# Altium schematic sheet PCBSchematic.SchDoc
size Letter; SheetNumber: 1; SheetTotal: 1
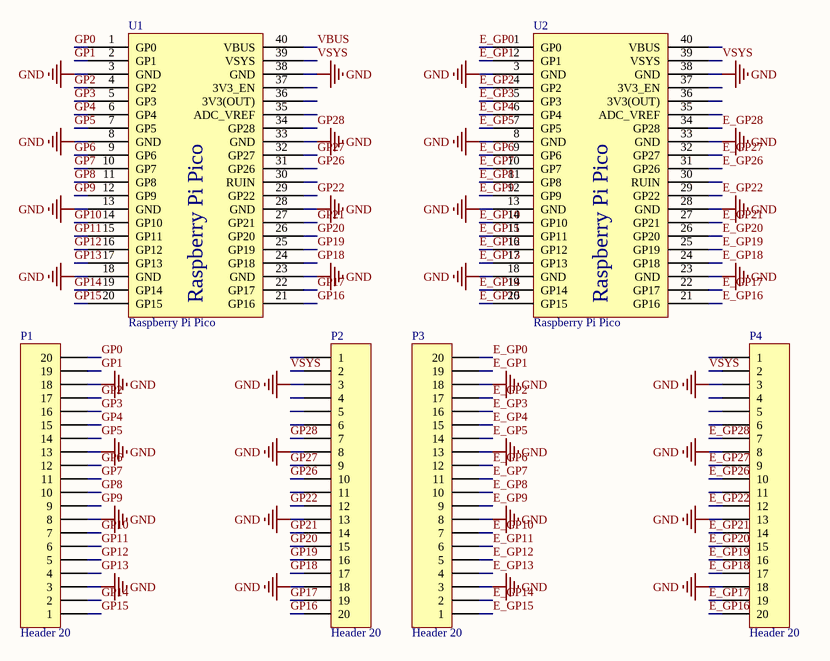
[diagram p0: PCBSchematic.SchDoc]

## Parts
P1  Header 20  [HDR1X20]
P2  Header 20  [HDR1X20]
P3  Header 20  [HDR1X20]
P4  Header 20  [HDR1X20]
U1  Raspberry Pi Pico  [Raspberry Pi Pico]
U2  Raspberry Pi Pico  [Raspberry Pi Pico]

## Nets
GND: P1.3 P1.8 P1.13 P1.18 P2.3 P2.8 P2.13 P2.18 P3.3 P3.8 P3.13 P3.18 P4.3 P4.8 P4.13 P4.18 U1.3(GND) U1.8(GND) U1.13(GND) U1.18(GND) U1.23(GND) U1.28(GND) U1.33(GND) U1.38(GND) U2.3(GND) U2.8(GND) U2.13(GND) U2.18(GND) U2.23(GND) U2.28(GND) U2.33(GND) U2.38(GND)
E_GP0: P3.20 U2.1(GP0)
E_GP1: P3.19 U2.2(GP1)
E_GP2: P3.17 U2.4(GP2)
E_GP3: P3.16 U2.5(GP3)
E_GP4: P3.15 U2.6(GP4)
E_GP5: P3.14 U2.7(GP5)
E_GP6: P3.12 U2.9(GP6)
E_GP7: P3.11 U2.10(GP7)
E_GP8: P3.10 U2.11(GP8)
E_GP9: P3.9 U2.12(GP9)
E_GP10: P3.7 U2.14(GP10)
E_GP11: P3.6 U2.15(GP11)
E_GP12: P3.5 U2.16(GP12)
E_GP13: P3.4 U2.17(GP13)
E_GP14: P3.2 U2.19(GP14)
E_GP15: P3.1 U2.20(GP15)
E_GP16: P4.20 U2.21(GP16)
E_GP17: P4.19 U2.22(GP17)
E_GP18: P4.17 U2.24(GP18)
E_GP19: P4.16 U2.25(GP19)
E_GP20: P4.15 U2.26(GP20)
E_GP21: P4.14 U2.27(GP21)
E_GP22: P4.12 U2.29(GP22)
E_GP26: P4.10 U2.31(GP26)
E_GP27: P4.9 U2.32(GP27)
E_GP28: P4.7 U2.34(GP28)
GP0: P1.20 U1.1(GP0)
GP1: P1.19 U1.2(GP1)
GP2: P1.17 U1.4(GP2)
GP3: P1.16 U1.5(GP3)
GP4: P1.15 U1.6(GP4)
GP5: P1.14 U1.7(GP5)
GP6: P1.12 U1.9(GP6)
GP7: P1.11 U1.10(GP7)
GP8: P1.10 U1.11(GP8)
GP9: P1.9 U1.12(GP9)
GP10: P1.7 U1.14(GP10)
GP11: P1.6 U1.15(GP11)
GP12: P1.5 U1.16(GP12)
GP13: P1.4 U1.17(GP13)
GP14: P1.2 U1.19(GP14)
GP15: P1.1 U1.20(GP15)
GP16: P2.20 U1.21(GP16)
GP17: P2.19 U1.22(GP17)
GP18: P2.17 U1.24(GP18)
GP19: P2.16 U1.25(GP19)
GP20: P2.15 U1.26(GP20)
GP21: P2.14 U1.27(GP21)
GP22: P2.12 U1.29(GP22)
GP26: P2.10 U1.31(GP26)
GP27: P2.9 U1.32(GP27)
GP28: P2.7 U1.34(GP28)
VBUS: U1.40(VBUS)
VSYS: P2.2 P4.2 U1.39(VSYS) U2.39(VSYS)

Not connected (* = marked no-connect by the designer): P2 1 4 5 6 11; P4 1 4 5 6 11; U1 30(RUIN) 35(ADC_VREF) 36(3V3(OUT)) 37(3V3_EN); U2 30(RUIN) 35(ADC_VREF) 36(3V3(OUT)) 37(3V3_EN) 40(VBUS)

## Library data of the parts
P1-P4 = Header 20: Header, 20-Pin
